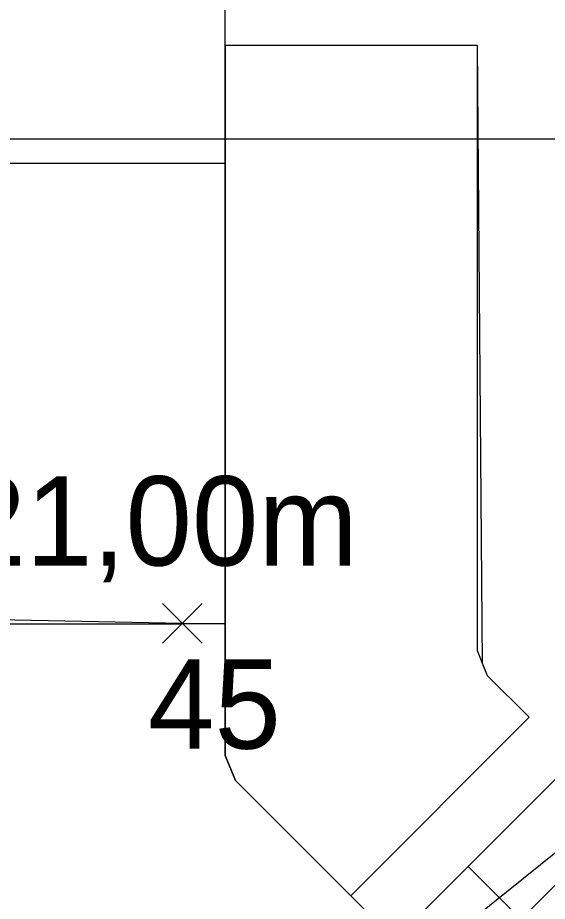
# Model space of a CAD drawing. Extents: x -263964 to -263544, y -1242317 to -1242020.
# Drawn here: x -263906.99 to -263895.13, y -1242227.54 to -1242207.77 of the extents above; entities that cross this region are included whole.
import ezdxf

# ---------------------------------------------------------------- set-up
doc = ezdxf.new("R2010")
doc.units = 0
for name, color, linetype in [('KFA_KOORDINACNA_SITUACIA_DSP_SEDA', 7, 'Continuous'), ('KFA_SO_50-1-II_BODY', 7, 'Continuous'), ('KFA_SO_50-1-II_VODOVODNE_PRIPOJKY', 7, 'Continuous'), ('POPIS', 7, 'Continuous')]:
    doc.layers.add(name, color=color, linetype=linetype)

msp = doc.modelspace()

# ---------------------------------------------------------------- linework, layer by layer
at = {"layer": 'KFA_KOORDINACNA_SITUACIA_DSP_SEDA'}
for p, q in [((-263902.343, -1242208.394), (-263902.343, -1242224.282)), ((-263896.693, -1242208.394), (-263902.343, -1242208.394)), ((-263896.578, -1242222.219), (-263896.693, -1242208.394)), ((-263903.343, -1242211.032), (-263921.351, -1242211.032)), ((-263902.343, -1242211.032), (-263903.343, -1242211.032)), ((-263923.393, -1242221.332), (-263903.343, -1242221.332)), ((-263889.023, -1242221.253), (-263906.365, -1242238.596)), ((-263902.343, -1242221.332), (-263903.343, -1242221.332)), ((-263896.463, -1242222.496), (-263896.578, -1242222.219)), ((-263895.535, -1242223.424), (-263896.463, -1242222.496)), ((-263899.53, -1242227.419), (-263895.535, -1242223.424)), ((-263902.343, -1242224.282), (-263902.113, -1242224.837)), ((-263902.113, -1242224.837), (-263899.53, -1242227.419))]:
    msp.add_line(p, q, dxfattribs=at)
for points in [[(-263816.02, -1242224.432), (-263887.916, -1242224.432), (-263888.26, -1242224.088), (-263889.254, -1242226.488), (-263890.391, -1242225.351), (-263894.351, -1242229.311), (-263896.896, -1242226.765), (-263892.937, -1242222.806), (-263894.073, -1242221.669), (-263891.673, -1242220.675), (-263892.018, -1242220.33), (-263892.018, -1242181.432), (-263893.618, -1242181.432), (-263893.618, -1242147.332), (-263892.018, -1242147.332), (-263892.018, -1242108.434)], [(-263898.543, -1242228.407), (-263902.112, -1242224.837), (-263902.343, -1242224.282), (-263902.343, -1242203.332), (-263909.043, -1242203.332)], [(-263891.673, -1242220.675), (-263894.073, -1242221.669), (-263892.937, -1242222.806), (-263898.544, -1242228.407)], [(-263903.277, -1242233.148), (-263900.731, -1242235.694), (-263890.333, -1242222.748), (-263903.277, -1242233.148)]]:
    msp.add_lwpolyline(points, dxfattribs=at)
for points in [[(-263893.618, -1242118.282), (-263916.093, -1242118.282), (-263916.093, -1242175.482), (-263914.293, -1242175.482), (-263914.293, -1242210.482), (-263893.618, -1242210.482), (-263893.618, -1242166.382), (-263900.043, -1242166.382), (-263900.043, -1242162.382), (-263893.618, -1242162.382)], [(-263896.693, -1242208.394), (-263902.343, -1242208.394), (-263902.343, -1242224.282), (-263902.113, -1242224.837), (-263899.53, -1242227.419), (-263895.535, -1242223.424), (-263896.463, -1242222.496), (-263896.693, -1242221.942)]]:
    msp.add_lwpolyline(points, close=True, dxfattribs=at)
at = {"layer": 'KFA_SO_50-1-II_BODY'}
for p, q in [((-263903.744, -1242221.764), (-263902.86, -1242220.88)), ((-263902.86, -1242221.764), (-263903.744, -1242220.88))]:
    msp.add_line(p, q, dxfattribs=at)
at = {"layer": 'KFA_SO_50-1-II_VODOVODNE_PRIPOJKY'}
msp.add_lwpolyline([(-263924.296, -1242220.899), (-263923.926, -1242220.907), (-263903.302, -1242221.322)], dxfattribs=at)

# ---------------------------------------------------------------- texts
at = {"layer": 'KFA_SO_50-1-II_BODY'}
msp.add_text('45', height=2, dxfattribs=at).set_placement((-263904.068, -1242224.127))
at = {"layer": 'POPIS'}
msp.add_text('HDPE Ø63mm - 21,00m', height=2, dxfattribs=at).set_placement((-263928.352, -1242220.03))

doc.saveas('drawing.dxf')
